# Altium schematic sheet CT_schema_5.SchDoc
size 255 x 245 mm
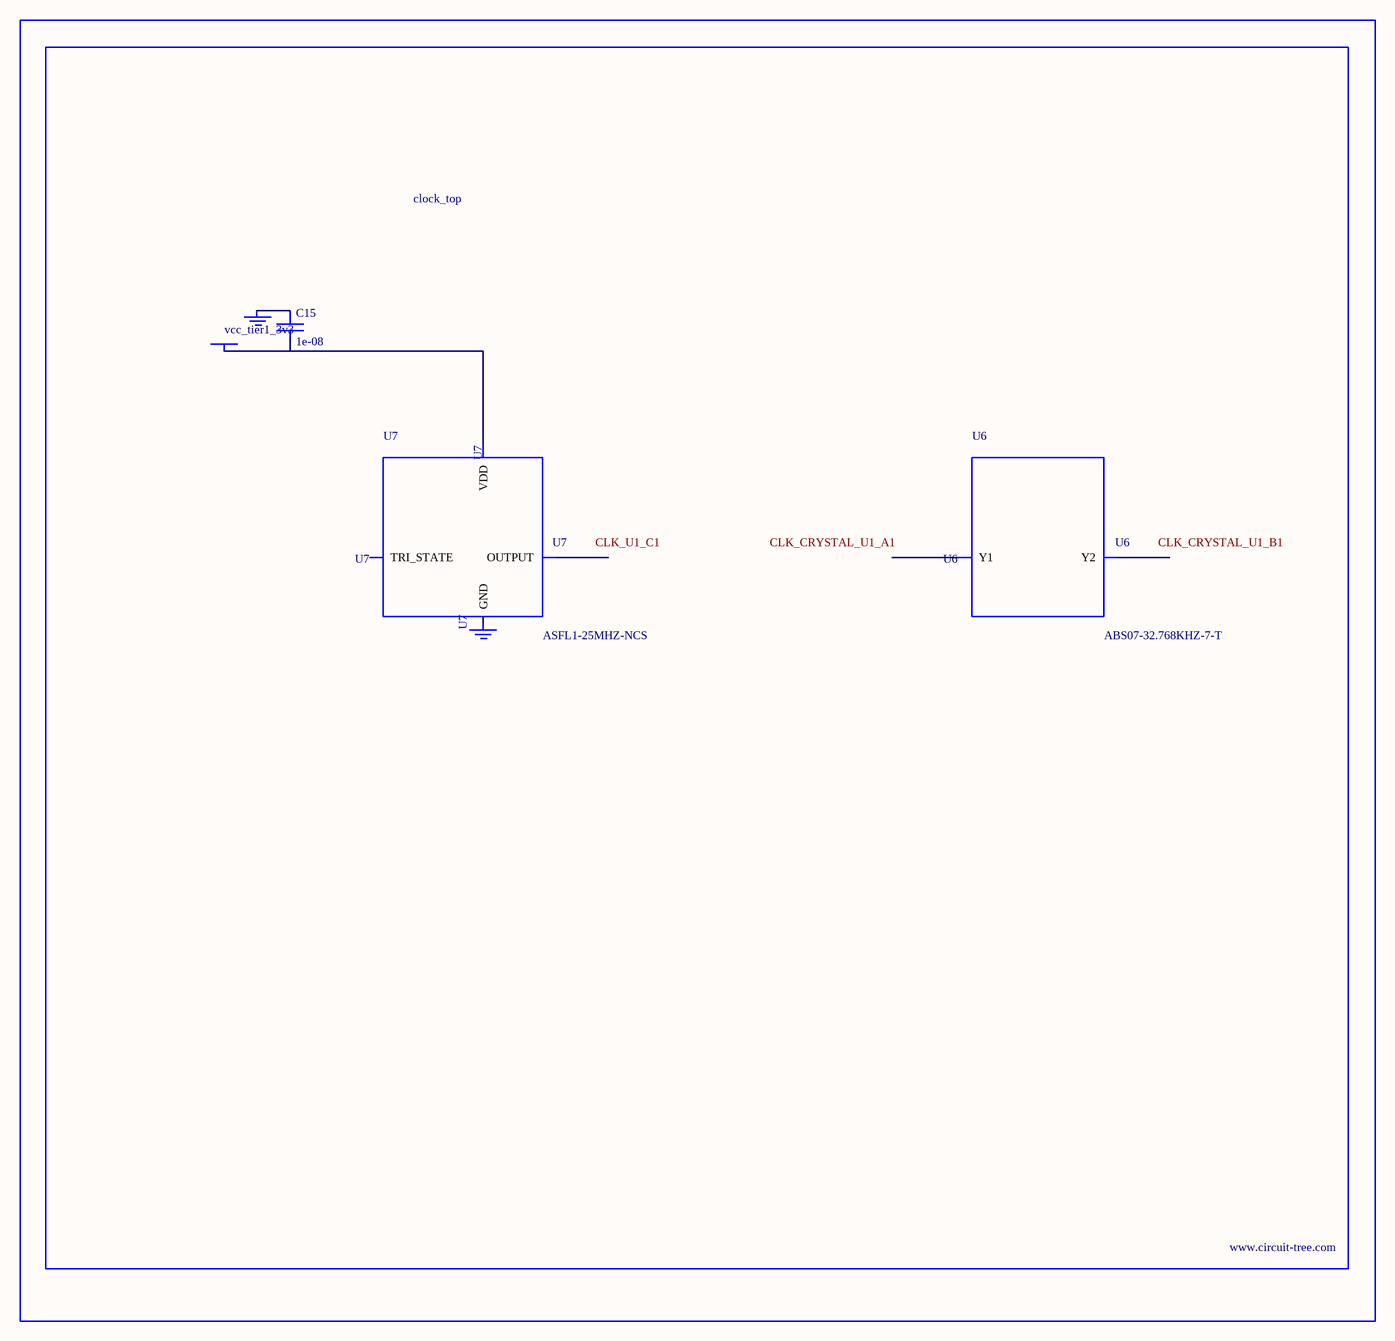
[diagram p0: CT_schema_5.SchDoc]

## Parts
BORDER4  (no value)
C15  1e-08  [C0402]
GND_INSTANCE_4_0  (no value)
GND_INSTANCE_4_1  (no value)
POWER_INSTANCE_4_0  vcc_tier1_3v3
U6  ABS07-32.768KHZ-7-T  [ABS07-32.768KHZ-7-T]
U7  ASFL1-25MHZ-NCS  [ASFL1]

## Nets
NetC15_1: C15.1 GND_INSTANCE_4_0.0(GND)
NetC15_2: C15.2 POWER_INSTANCE_4_0.0(PWR) U7.4(VDD)

Not connected (* = marked no-connect by the designer): GND_INSTANCE_4_1 0(GND); U6 1(Y1) 2(Y2); U7 1(TRI_STATE) 2(GND) 3(OUTPUT)

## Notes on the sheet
- Labels drawn without touching a wire or pin: CLK_CRYSTAL_U1_A1, CLK_CRYSTAL_U1_B1, CLK_U1_C1

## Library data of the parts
BORDER4 = BORDER_PAGE4
C15 = C0402C103K3RAC
GND_INSTANCE_4_0 GND_INSTANCE_4_1 = GND
POWER_INSTANCE_4_0 = PWR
